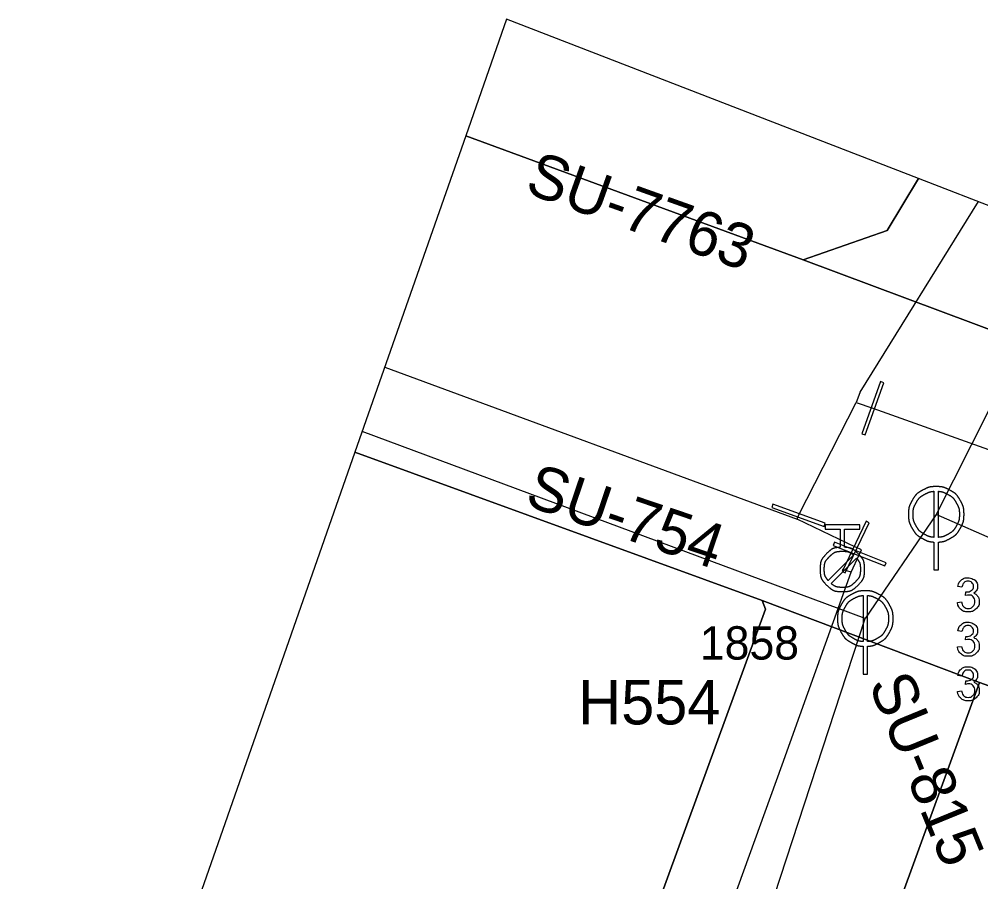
# Model space of a CAD drawing. Extents: x -562248 to -562040, y -1079385 to -1079027.
# Drawn here: x -562150.04 to -562106.79, y -1079065.59 to -1079026.78 of the extents above; entities that cross this region are included whole.
import ezdxf

# ---------------------------------------------------------------- set-up
doc = ezdxf.new("R2010")
doc.units = 0
for name, color, linetype in [('Armatura - popis', 7, 'Continuous'), ('Armatura vodovodní', 7, 'Continuous'), ('Default', 7, 'Continuous'), ('Hydrant', 7, 'Continuous'), ('Kanalizační stoka', 7, 'Continuous'), ('Kanalizační šachta', 7, 'Continuous'), ('Označení hydrantu', 7, 'Continuous'), ('Parcela-polygon', 7, 'Continuous'), ('Popis šachty', 7, 'Continuous'), ('Vodovodní řad', 7, 'Continuous')]:
    doc.layers.add(name, color=color, linetype=linetype)

msp = doc.modelspace()

# ---------------------------------------------------------------- linework, layer by layer
at = {"layer": 'Armatura vodovodní'}
for points in [[(-562111.993, -1079045.489), (-562111.151, -1079043.135), (-562111.298, -1079043.083), (-562112.14, -1079045.437)], [(-562113.837, -1079049.605), (-562113.784, -1079049.458), (-562116.135, -1079048.609), (-562116.188, -1079048.756)], [(-562112.883, -1079051.694), (-562111.803, -1079049.439), (-562111.944, -1079049.372), (-562113.024, -1079051.626)], [(-562111.107, -1079051.382), (-562111.049, -1079051.236), (-562113.372, -1079050.312), (-562113.429, -1079050.457)]]:
    msp.add_lwpolyline(points, close=True, dxfattribs=at)
at = {"layer": 'Default'}
for points in [[(-562108.79, -1079047.81), (-562109.002, -1079047.81), (-562109.207, -1079047.864), (-562109.405, -1079047.971)], [(-562108.176, -1079047.971), (-562108.375, -1079047.864), (-562108.58, -1079047.81), (-562108.79, -1079047.81)], [(-562109.405, -1079047.971), (-562109.604, -1079048.079), (-562109.759, -1079048.232), (-562109.872, -1079048.433)], [(-562109.693, -1079048.539), (-562109.601, -1079048.372), (-562109.471, -1079048.244), (-562109.305, -1079048.154)], [(-562109.305, -1079048.154), (-562109.162, -1079048.078), (-562109.024, -1079048.034), (-562108.893, -1079048.022)], [(-562108.687, -1079048.022), (-562108.556, -1079048.034), (-562108.419, -1079048.078), (-562108.277, -1079048.154)], [(-562108.277, -1079048.154), (-562108.111, -1079048.244), (-562107.981, -1079048.372), (-562107.888, -1079048.539)], [(-562107.708, -1079048.433), (-562107.821, -1079048.232), (-562107.977, -1079048.079), (-562108.176, -1079047.971)], [(-562109.872, -1079048.433), (-562109.984, -1079048.633), (-562110.04, -1079048.842), (-562110.04, -1079049.06)], [(-562109.832, -1079049.06), (-562109.832, -1079048.879), (-562109.786, -1079048.706), (-562109.693, -1079048.539)], [(-562107.888, -1079048.539), (-562107.794, -1079048.706), (-562107.748, -1079048.879), (-562107.748, -1079049.06)], [(-562107.54, -1079049.06), (-562107.54, -1079048.842), (-562107.596, -1079048.633), (-562107.708, -1079048.433)], [(-562110.04, -1079049.06), (-562110.04, -1079049.276), (-562109.985, -1079049.484), (-562109.875, -1079049.683)], [(-562109.696, -1079049.578), (-562109.787, -1079049.413), (-562109.832, -1079049.241), (-562109.832, -1079049.06)], [(-562107.748, -1079049.06), (-562107.748, -1079049.241), (-562107.793, -1079049.413), (-562107.884, -1079049.578)], [(-562107.705, -1079049.683), (-562107.595, -1079049.484), (-562107.54, -1079049.276), (-562107.54, -1079049.06)], [(-562109.31, -1079049.961), (-562109.476, -1079049.87), (-562109.605, -1079049.742), (-562109.696, -1079049.578)], [(-562107.884, -1079049.578), (-562107.975, -1079049.742), (-562108.103, -1079049.87), (-562108.268, -1079049.961)], [(-562109.875, -1079049.683), (-562109.765, -1079049.881), (-562109.611, -1079050.035), (-562109.413, -1079050.144)], [(-562108.893, -1079050.095), (-562109.029, -1079050.085), (-562109.168, -1079050.041), (-562109.31, -1079049.961)], [(-562108.268, -1079049.961), (-562108.411, -1079050.041), (-562108.551, -1079050.085), (-562108.687, -1079050.095)], [(-562108.167, -1079050.144), (-562107.969, -1079050.035), (-562107.815, -1079049.881), (-562107.705, -1079049.683)], [(-562109.413, -1079050.144), (-562109.238, -1079050.242), (-562109.065, -1079050.296), (-562108.893, -1079050.308)], [(-562108.687, -1079050.308), (-562108.515, -1079050.296), (-562108.342, -1079050.242), (-562108.167, -1079050.144)], [(-562113.721, -1079050.828), (-562113.915, -1079051.023), (-562114.012, -1079051.26), (-562114.012, -1079051.537)], [(-562113.106, -1079050.539), (-562113.344, -1079050.557), (-562113.549, -1079050.653), (-562113.721, -1079050.828)], [(-562113.589, -1079050.958), (-562113.431, -1079050.8), (-562113.239, -1079050.721), (-562113.014, -1079050.721)], [(-562113.014, -1079050.721), (-562112.82, -1079050.721), (-562112.651, -1079050.779), (-562112.506, -1079050.896)], [(-562112.303, -1079050.828), (-562112.475, -1079050.655), (-562112.68, -1079050.558), (-562112.918, -1079050.539)], [(-562112.012, -1079051.537), (-562112.012, -1079051.26), (-562112.109, -1079051.023), (-562112.303, -1079050.828)], [(-562113.826, -1079051.533), (-562113.826, -1079051.308), (-562113.747, -1079051.116), (-562113.589, -1079050.958)], [(-562112.373, -1079051.029), (-562112.259, -1079051.172), (-562112.201, -1079051.34), (-562112.201, -1079051.533)], [(-562114.012, -1079051.537), (-562114.012, -1079051.813), (-562113.914, -1079052.048), (-562113.719, -1079052.243)], [(-562113.651, -1079052.041), (-562113.768, -1079051.896), (-562113.826, -1079051.727), (-562113.826, -1079051.533)], [(-562112.201, -1079051.533), (-562112.201, -1079051.758), (-562112.281, -1079051.95), (-562112.44, -1079052.108)], [(-562112.305, -1079052.243), (-562112.11, -1079052.048), (-562112.012, -1079051.813), (-562112.012, -1079051.537)], [(-562113.014, -1079052.346), (-562113.207, -1079052.346), (-562113.375, -1079052.288), (-562113.518, -1079052.174)], [(-562112.44, -1079052.108), (-562112.599, -1079052.266), (-562112.79, -1079052.346), (-562113.014, -1079052.346)], [(-562113.719, -1079052.243), (-562113.524, -1079052.438), (-562113.289, -1079052.535), (-562113.014, -1079052.535)], [(-562112.595, -1079052.661), (-562112.794, -1079052.769), (-562112.949, -1079052.922), (-562113.062, -1079053.123)], [(-562113.014, -1079052.535), (-562112.737, -1079052.535), (-562112.5, -1079052.438), (-562112.305, -1079052.243)], [(-562111.98, -1079052.5), (-562112.192, -1079052.5), (-562112.397, -1079052.554), (-562112.595, -1079052.661)], [(-562111.366, -1079052.661), (-562111.565, -1079052.554), (-562111.77, -1079052.5), (-562111.98, -1079052.5)], [(-562110.898, -1079053.123), (-562111.011, -1079052.922), (-562111.167, -1079052.769), (-562111.366, -1079052.661)], [(-562112.883, -1079053.229), (-562112.791, -1079053.062), (-562112.661, -1079052.934), (-562112.495, -1079052.844)], [(-562112.495, -1079052.844), (-562112.352, -1079052.768), (-562112.214, -1079052.724), (-562112.083, -1079052.712)], [(-562111.877, -1079052.712), (-562111.746, -1079052.724), (-562111.609, -1079052.768), (-562111.467, -1079052.844)], [(-562111.467, -1079052.844), (-562111.301, -1079052.934), (-562111.171, -1079053.062), (-562111.078, -1079053.229)], [(-562113.062, -1079053.123), (-562113.174, -1079053.323), (-562113.23, -1079053.532), (-562113.23, -1079053.75)], [(-562113.022, -1079053.75), (-562113.022, -1079053.569), (-562112.976, -1079053.396), (-562112.883, -1079053.229)], [(-562111.078, -1079053.229), (-562110.984, -1079053.396), (-562110.938, -1079053.569), (-562110.938, -1079053.75)], [(-562110.73, -1079053.75), (-562110.73, -1079053.532), (-562110.786, -1079053.323), (-562110.898, -1079053.123)], [(-562113.23, -1079053.75), (-562113.23, -1079053.966), (-562113.175, -1079054.174), (-562113.065, -1079054.373)], [(-562112.886, -1079054.268), (-562112.977, -1079054.103), (-562113.022, -1079053.931), (-562113.022, -1079053.75)], [(-562110.938, -1079053.75), (-562110.938, -1079053.931), (-562110.983, -1079054.103), (-562111.074, -1079054.268)], [(-562110.895, -1079054.373), (-562110.785, -1079054.174), (-562110.73, -1079053.966), (-562110.73, -1079053.75)], [(-562113.065, -1079054.373), (-562112.955, -1079054.571), (-562112.801, -1079054.725), (-562112.603, -1079054.834)], [(-562112.5, -1079054.651), (-562112.666, -1079054.56), (-562112.795, -1079054.432), (-562112.886, -1079054.268)], [(-562111.074, -1079054.268), (-562111.165, -1079054.432), (-562111.293, -1079054.56), (-562111.458, -1079054.651)], [(-562111.357, -1079054.834), (-562111.159, -1079054.725), (-562111.005, -1079054.571), (-562110.895, -1079054.373)], [(-562112.083, -1079054.785), (-562112.219, -1079054.775), (-562112.358, -1079054.731), (-562112.5, -1079054.651)], [(-562111.458, -1079054.651), (-562111.601, -1079054.731), (-562111.741, -1079054.775), (-562111.877, -1079054.785)], [(-562112.603, -1079054.834), (-562112.428, -1079054.932), (-562112.255, -1079054.986), (-562112.083, -1079054.998)], [(-562111.877, -1079054.998), (-562111.705, -1079054.986), (-562111.532, -1079054.932), (-562111.357, -1079054.834)]]:
    msp.add_open_spline(points, degree=2, dxfattribs=at)
at = {"layer": 'Hydrant'}
for points in [[(-562112.918, -1079050.539), (-562112.918, -1079049.723), (-562112.231, -1079049.723), (-562112.231, -1079049.535), (-562113.793, -1079049.535), (-562113.793, -1079049.723), (-562113.106, -1079049.723), (-562113.106, -1079050.539)], [(-562112.506, -1079050.896), (-562113.651, -1079052.041)], [(-562113.518, -1079052.174), (-562112.373, -1079051.029)]]:
    msp.add_lwpolyline(points, dxfattribs=at)
at = {"layer": 'Kanalizační stoka'}
for points in [[(-562104.87, -1079041.277), (-562108.79, -1079049.06)], [(-562108.79, -1079049.06), (-562111.98, -1079053.75), (-562134.615, -1079045.333)], [(-562087.687, -1079058.312), (-562108.79, -1079049.06)], [(-562125.61, -1079095.35), (-562111.98, -1079053.75)]]:
    msp.add_lwpolyline(points, dxfattribs=at)
at = {"layer": 'Kanalizační šachta'}
for points in [[(-562108.893, -1079048.022), (-562108.893, -1079050.095)], [(-562108.687, -1079050.095), (-562108.687, -1079048.022)], [(-562108.893, -1079051.56), (-562108.687, -1079051.56), (-562108.687, -1079050.308)], [(-562108.893, -1079050.308), (-562108.893, -1079051.56)], [(-562112.083, -1079052.712), (-562112.083, -1079054.785)], [(-562111.877, -1079054.785), (-562111.877, -1079052.712)], [(-562112.083, -1079056.25), (-562111.877, -1079056.25), (-562111.877, -1079054.998)], [(-562112.083, -1079054.998), (-562112.083, -1079056.25)]]:
    msp.add_lwpolyline(points, dxfattribs=at)
at = {"layer": 'Parcela-polygon'}
for p, q in [((-562129.957, -1079032.03), (-562134.941, -1079046.267)), ((-562098.282, -1079038.318), (-562109.587, -1079033.946)), ((-562134.941, -1079046.267), (-562150.044, -1079089.409))]:
    msp.add_line(p, q, dxfattribs=at)
for points in [[(-562109.587, -1079033.946), (-562128.12, -1079026.78), (-562129.957, -1079032.03)], [(-562129.957, -1079032.03), (-562114.77, -1079037.6), (-562111, -1079036.29), (-562109.587, -1079033.946)], [(-562084.12, -1079049.039), (-562097.72, -1079043.98), (-562114.77, -1079037.6), (-562129.957, -1079032.03)], [(-562109.587, -1079033.946), (-562111, -1079036.29), (-562114.77, -1079037.6), (-562097.72, -1079043.98), (-562099.23, -1079039.9), (-562098.282, -1079038.318)], [(-562150.044, -1079089.409), (-562131.3, -1079096.35), (-562129.6, -1079089.95), (-562127.9, -1079084.66), (-562116.47, -1079053.33), (-562116.62, -1079052.94), (-562134.941, -1079046.267)], [(-562134.941, -1079046.267), (-562116.62, -1079052.94), (-562106.84, -1079056.62), (-562089.427, -1079062.836)], [(-562122.69, -1079105.05), (-562122.05, -1079101.16), (-562121.03, -1079096.76), (-562119.65, -1079091.82), (-562106.84, -1079056.62), (-562116.62, -1079052.94), (-562116.47, -1079053.33), (-562127.9, -1079084.66), (-562129.6, -1079089.95), (-562131.3, -1079096.35), (-562132.29, -1079100.17), (-562132.68, -1079103.22)], [(-562089.427, -1079062.836), (-562106.84, -1079056.62), (-562119.65, -1079091.82), (-562121.03, -1079096.76), (-562122.05, -1079101.16), (-562122.69, -1079105.05), (-562122.92, -1079108.96), (-562097.98, -1079104.526)]]:
    msp.add_lwpolyline(points, dxfattribs=at)
at = {"layer": 'Popis šachty'}
for points in [[(-562107.633, -1079052.338), (-562107.817, -1079052.305)], [(-562107.473, -1079052.711), (-562107.452, -1079052.55)], [(-562107.836, -1079053.024), (-562107.652, -1079053)], [(-562107.633, -1079054.338), (-562107.817, -1079054.305)], [(-562107.473, -1079054.711), (-562107.452, -1079054.55)], [(-562107.836, -1079055.024), (-562107.652, -1079055)], [(-562107.633, -1079056.338), (-562107.817, -1079056.305)], [(-562107.473, -1079056.711), (-562107.452, -1079056.55)], [(-562107.836, -1079057.024), (-562107.652, -1079057)]]:
    msp.add_lwpolyline(points, dxfattribs=at)
for points in [[(-562107.817, -1079052.305), (-562107.784, -1079052.12), (-562107.664, -1079052.018), (-562107.544, -1079051.916), (-562107.366, -1079051.916), (-562107.243, -1079051.916), (-562107.14, -1079051.969), (-562107.036, -1079052.022), (-562106.982, -1079052.112), (-562106.927, -1079052.203), (-562106.927, -1079052.305), (-562106.927, -1079052.403), (-562106.979, -1079052.482), (-562107.031, -1079052.562), (-562107.133, -1079052.609), (-562107, -1079052.64), (-562106.927, -1079052.736), (-562106.854, -1079052.833), (-562106.854, -1079052.978), (-562106.854, -1079053.174), (-562106.997, -1079053.311), (-562107.14, -1079053.447), (-562107.359, -1079053.447), (-562107.556, -1079053.447), (-562107.687, -1079053.329), (-562107.817, -1079053.212), (-562107.836, -1079053.024)], [(-562107.452, -1079052.55), (-562107.434, -1079052.552), (-562107.422, -1079052.552), (-562107.305, -1079052.552), (-562107.211, -1079052.49), (-562107.117, -1079052.429), (-562107.117, -1079052.301), (-562107.117, -1079052.2), (-562107.185, -1079052.134), (-562107.254, -1079052.067), (-562107.362, -1079052.067), (-562107.47, -1079052.067), (-562107.541, -1079052.135), (-562107.613, -1079052.203), (-562107.633, -1079052.338)], [(-562107.652, -1079053), (-562107.62, -1079053.157), (-562107.544, -1079053.226), (-562107.468, -1079053.295), (-562107.358, -1079053.295), (-562107.228, -1079053.295), (-562107.138, -1079053.205), (-562107.049, -1079053.115), (-562107.049, -1079052.982), (-562107.049, -1079052.855), (-562107.132, -1079052.773), (-562107.215, -1079052.69), (-562107.343, -1079052.69), (-562107.395, -1079052.69), (-562107.473, -1079052.711)], [(-562107.817, -1079054.305), (-562107.784, -1079054.12), (-562107.664, -1079054.018), (-562107.544, -1079053.916), (-562107.366, -1079053.916), (-562107.243, -1079053.916), (-562107.14, -1079053.969), (-562107.036, -1079054.022), (-562106.982, -1079054.112), (-562106.927, -1079054.203), (-562106.927, -1079054.305), (-562106.927, -1079054.403), (-562106.979, -1079054.482), (-562107.031, -1079054.562), (-562107.133, -1079054.609), (-562107, -1079054.64), (-562106.927, -1079054.736), (-562106.854, -1079054.833), (-562106.854, -1079054.978), (-562106.854, -1079055.174), (-562106.997, -1079055.311), (-562107.14, -1079055.447), (-562107.359, -1079055.447), (-562107.556, -1079055.447), (-562107.687, -1079055.329), (-562107.817, -1079055.212), (-562107.836, -1079055.024)], [(-562107.452, -1079054.55), (-562107.434, -1079054.552), (-562107.422, -1079054.552), (-562107.305, -1079054.552), (-562107.211, -1079054.49), (-562107.117, -1079054.429), (-562107.117, -1079054.301), (-562107.117, -1079054.2), (-562107.185, -1079054.134), (-562107.254, -1079054.067), (-562107.362, -1079054.067), (-562107.47, -1079054.067), (-562107.541, -1079054.135), (-562107.613, -1079054.203), (-562107.633, -1079054.338)], [(-562107.652, -1079055), (-562107.62, -1079055.157), (-562107.544, -1079055.226), (-562107.468, -1079055.295), (-562107.358, -1079055.295), (-562107.228, -1079055.295), (-562107.138, -1079055.205), (-562107.049, -1079055.115), (-562107.049, -1079054.982), (-562107.049, -1079054.855), (-562107.132, -1079054.773), (-562107.215, -1079054.69), (-562107.343, -1079054.69), (-562107.395, -1079054.69), (-562107.473, -1079054.711)], [(-562107.817, -1079056.305), (-562107.784, -1079056.12), (-562107.664, -1079056.018), (-562107.544, -1079055.916), (-562107.366, -1079055.916), (-562107.243, -1079055.916), (-562107.14, -1079055.969), (-562107.036, -1079056.022), (-562106.982, -1079056.112), (-562106.927, -1079056.203), (-562106.927, -1079056.305), (-562106.927, -1079056.403), (-562106.979, -1079056.482), (-562107.031, -1079056.562), (-562107.133, -1079056.609), (-562107, -1079056.64), (-562106.927, -1079056.736), (-562106.854, -1079056.833), (-562106.854, -1079056.978), (-562106.854, -1079057.174), (-562106.997, -1079057.311), (-562107.14, -1079057.447), (-562107.359, -1079057.447), (-562107.556, -1079057.447), (-562107.687, -1079057.329), (-562107.817, -1079057.212), (-562107.836, -1079057.024)], [(-562107.452, -1079056.55), (-562107.434, -1079056.552), (-562107.422, -1079056.552), (-562107.305, -1079056.552), (-562107.211, -1079056.49), (-562107.117, -1079056.429), (-562107.117, -1079056.301), (-562107.117, -1079056.2), (-562107.185, -1079056.134), (-562107.254, -1079056.067), (-562107.362, -1079056.067), (-562107.47, -1079056.067), (-562107.541, -1079056.135), (-562107.613, -1079056.203), (-562107.633, -1079056.338)], [(-562107.652, -1079057), (-562107.62, -1079057.157), (-562107.544, -1079057.226), (-562107.468, -1079057.295), (-562107.358, -1079057.295), (-562107.228, -1079057.295), (-562107.138, -1079057.205), (-562107.049, -1079057.115), (-562107.049, -1079056.982), (-562107.049, -1079056.855), (-562107.132, -1079056.773), (-562107.215, -1079056.69), (-562107.343, -1079056.69), (-562107.395, -1079056.69), (-562107.473, -1079056.711)]]:
    msp.add_open_spline(points, degree=3, dxfattribs=at)
at = {"layer": 'Vodovodní řad'}
for points in [[(-562106.901, -1079034.985), (-562112.22, -1079043.56), (-562112.232, -1079043.592)], [(-562133.603, -1079042.443), (-562115.047, -1079049.276)], [(-562112.232, -1079043.592), (-562112.389, -1079044.02)], [(-562112.242, -1079050.849), (-562112.154, -1079050.657), (-562112.414, -1079050.533), (-562112.419, -1079050.53), (-562115.047, -1079049.276), (-562114.986, -1079049.107), (-562112.389, -1079044.02)], [(-562112.389, -1079044.02), (-562111.645, -1079044.286), (-562085.841, -1079053.513)], [(-562128.126, -1079096.082), (-562128.042, -1079095.79), (-562127.563, -1079094.412), (-562126.882, -1079092.296), (-562125.308, -1079086.997), (-562123.784, -1079082.313), (-562119.925, -1079072.045), (-562119.675, -1079071.286), (-562115.714, -1079060.331), (-562112.61, -1079051.657), (-562112.242, -1079050.849)], [(-562112.61, -1079051.657), (-562113.012, -1079051.535)]]:
    msp.add_lwpolyline(points, dxfattribs=at)

# ---------------------------------------------------------------- texts
at = {"layer": 'Armatura - popis'}
for s, rotation, p in [('SU-7763', 340.3232, (-562127.36, -1079034.562)), ('SU-754', 341.2742, (-562127.364, -1079048.626)), ('SU-815', 292.2406, (-562111.854, -1079056.681))]:
    msp.add_text(s, height=2, rotation=rotation, dxfattribs=at).set_placement(p)
at = {"layer": 'Označení hydrantu'}
msp.add_text('H554', height=2, dxfattribs=at).set_placement((-562124.894, -1079058.513))
at = {"layer": 'Popis šachty'}
msp.add_text('1858', height=1.5, dxfattribs=at).set_placement((-562119.425, -1079055.595))

doc.saveas('drawing.dxf')
